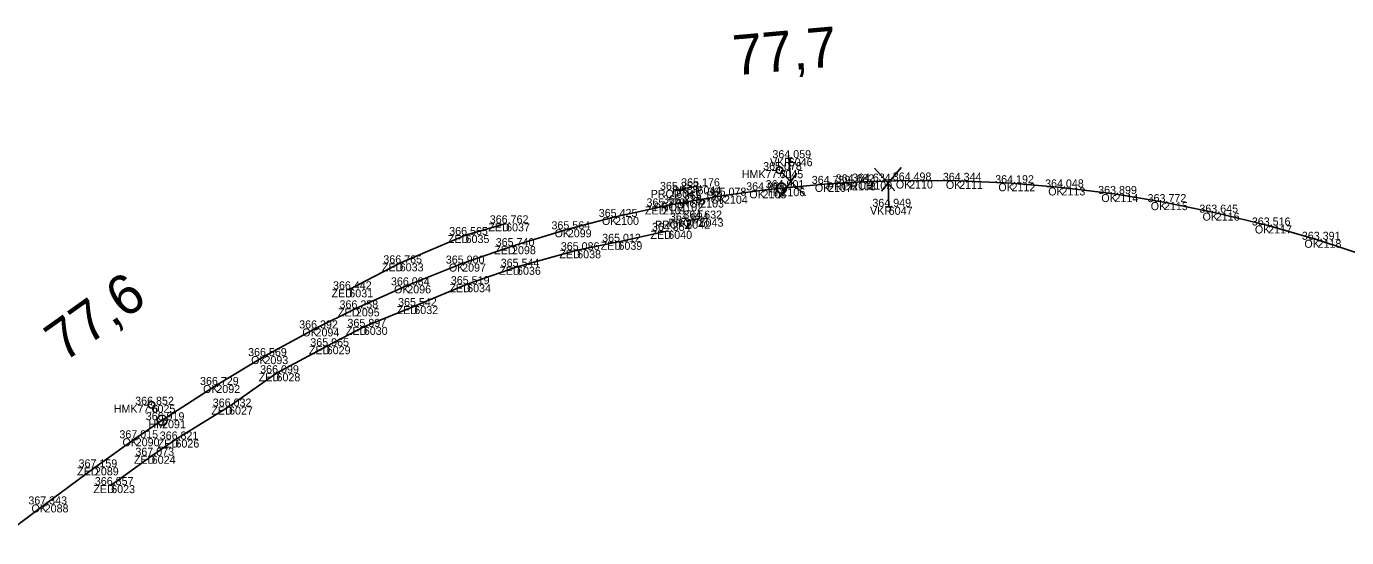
# Model space of a CAD drawing. Extents: x -621782 to -610392, y -1141853 to -1122321.
# Drawn here: x -616534.2 to -616336.3, y -1130256.3 to -1130179.7 of the extents above; entities that cross this region are included whole.
import ezdxf

# ---------------------------------------------------------------- set-up
doc = ezdxf.new("R2010")
doc.units = 0
for name, color, linetype in [('Vrstva 1', 7, 'Continuous'), ('Vrstva 13', 7, 'Continuous'), ('Vrstva 19', 7, 'Continuous'), ('Vrstva 4', 7, 'Continuous'), ('Vrstva 60', 7, 'Continuous'), ('Vrstva 61', 7, 'Continuous'), ('Vrstva 62', 7, 'Continuous'), ('Vrstva 7', 7, 'Continuous')]:
    doc.layers.add(name, color=color, linetype=linetype)

msp = doc.modelspace()

# ---------------------------------------------------------------- linework, layer by layer
at = {"layer": 'Vrstva 1'}
msp.add_lwpolyline([(-616538.07, -1130256.29), (-616531.48, -1130251.32), (-616523.95, -1130245.77), (-616517.83, -1130241.41), (-616513.88, -1130238.71), (-616505.74, -1130233.43), (-616498.53, -1130229.1), (-616490.87, -1130224.95), (-616484.82, -1130221.95), (-616477.11, -1130218.5), (-616468.88, -1130215.24), (-616461.4, -1130212.63), (-616453.04, -1130210.1), (-616445.94, -1130208.25), (-616438.79, -1130206.67), (-616436.33, -1130206.2), (-616433.19, -1130205.64), (-616429.62, -1130205.06), (-616423.84, -1130204.26), (-616421.01, -1130203.94), (-616414.01, -1130203.3), (-616410.42, -1130203.07), (-616407.97, -1130202.95), (-616401.86, -1130202.79), (-616394.36, -1130202.84), (-616386.5, -1130203.2), (-616379.01, -1130203.83), (-616371.06, -1130204.81), (-616363.65, -1130206.03), (-616355.88, -1130207.61), (-616348.02, -1130209.53), (-616340.61, -1130211.67), (-616333.02, -1130214.2)], dxfattribs=at)
at = {"layer": 'Vrstva 13'}
for points in [[(-616437.97, -1130210.33), (-616445.44, -1130211.97), (-616451.63, -1130213.24), (-616460.65, -1130215.72), (-616468.13, -1130218.33), (-616476.05, -1130221.6), (-616483.63, -1130224.72), (-616489.19, -1130227.62), (-616496.72, -1130231.67), (-616503.83, -1130236.66), (-616511.87, -1130241.6), (-616515.43, -1130244.03), (-616521.51, -1130248.43)], [(-616485.8, -1130219.1), (-616478.24, -1130215.2), (-616468.37, -1130210.96), (-616462.29, -1130209.21)]]:
    msp.add_lwpolyline(points, dxfattribs=at)
at = {"layer": 'Vrstva 19'}
for p, q in [((-616436.77, -1130204.2), (-616433.59, -1130203.66)), ((-616435.27, -1130208.81), (-616433.27, -1130208.5))]:
    msp.add_line(p, q, dxfattribs=at)
at = {"layer": 'Vrstva 4'}
for p, q in [((-616419.41, -1130199.4), (-616420.41, -1130199.49)), ((-616419.91, -1130199.45), (-616419.6, -1130202.95)), ((-616407.07, -1130200.93), (-616403.98, -1130204.35)), ((-616405.98, -1130204.4), (-616403.07, -1130200.82)), ((-616418.7, -1130201.7), (-616421.38, -1130205.45)), ((-616417.39, -1130205.1), (-616420.7, -1130201.88)), ((-616410.42, -1130203.07), (-616407.97, -1130202.95)), ((-616404.92, -1130206.73), (-616405.01, -1130203.21)), ((-616405.42, -1130206.74), (-616404.42, -1130206.71))]:
    msp.add_line(p, q, dxfattribs=at)
at = {"layer": 'Vrstva 60'}
for p, q in [((-616419.91, -1130199.45), (-616419.91, -1130199.45)), ((-616421.3, -1130201.24), (-616421.3, -1130201.24)), ((-616407.97, -1130202.95), (-616407.97, -1130202.95)), ((-616401.86, -1130202.79), (-616401.86, -1130202.79)), ((-616394.36, -1130202.84), (-616394.36, -1130202.84)), ((-616436.77, -1130204.2), (-616436.77, -1130204.2)), ((-616433.59, -1130203.66), (-616433.59, -1130203.66)), ((-616423.84, -1130204.26), (-616423.84, -1130204.26)), ((-616421.01, -1130203.94), (-616421.01, -1130203.94)), ((-616414.01, -1130203.3), (-616414.01, -1130203.3)), ((-616410.42, -1130203.07), (-616410.42, -1130203.07)), ((-616386.5, -1130203.2), (-616386.5, -1130203.2)), ((-616379.01, -1130203.83), (-616379.01, -1130203.83)), ((-616371.06, -1130204.81), (-616371.06, -1130204.81)), ((-616438.79, -1130206.67), (-616438.79, -1130206.67)), ((-616436.33, -1130206.2), (-616436.33, -1130206.2)), ((-616433.19, -1130205.64), (-616433.19, -1130205.64)), ((-616429.62, -1130205.06), (-616429.62, -1130205.06)), ((-616404.92, -1130206.73), (-616404.92, -1130206.73)), ((-616363.65, -1130206.03), (-616363.65, -1130206.03)), ((-616445.94, -1130208.25), (-616445.94, -1130208.25)), ((-616435.27, -1130208.81), (-616435.27, -1130208.81)), ((-616433.27, -1130208.5), (-616433.27, -1130208.5)), ((-616355.88, -1130207.61), (-616355.88, -1130207.61)), ((-616462.29, -1130209.21), (-616462.29, -1130209.21)), ((-616453.04, -1130210.1), (-616453.04, -1130210.1)), ((-616437.97, -1130210.33), (-616437.97, -1130210.33)), ((-616348.02, -1130209.53), (-616348.02, -1130209.53)), ((-616468.37, -1130210.96), (-616468.37, -1130210.96)), ((-616461.4, -1130212.63), (-616461.4, -1130212.63)), ((-616445.44, -1130211.97), (-616445.44, -1130211.97)), ((-616340.61, -1130211.67), (-616340.61, -1130211.67)), ((-616451.63, -1130213.24), (-616451.63, -1130213.24)), ((-616478.24, -1130215.2), (-616478.24, -1130215.2)), ((-616468.88, -1130215.24), (-616468.88, -1130215.24)), ((-616460.65, -1130215.72), (-616460.65, -1130215.72)), ((-616477.11, -1130218.5), (-616477.11, -1130218.5)), ((-616468.13, -1130218.33), (-616468.13, -1130218.33)), ((-616485.8, -1130219.1), (-616485.8, -1130219.1)), ((-616484.82, -1130221.95), (-616484.82, -1130221.95)), ((-616476.05, -1130221.6), (-616476.05, -1130221.6)), ((-616483.63, -1130224.72), (-616483.63, -1130224.72)), ((-616490.87, -1130224.95), (-616490.87, -1130224.95)), ((-616489.19, -1130227.62), (-616489.19, -1130227.62)), ((-616498.53, -1130229.1), (-616498.53, -1130229.1)), ((-616496.72, -1130231.67), (-616496.72, -1130231.67)), ((-616505.74, -1130233.43), (-616505.74, -1130233.43)), ((-616515.46, -1130236.39), (-616515.46, -1130236.39)), ((-616503.83, -1130236.66), (-616503.83, -1130236.66)), ((-616513.88, -1130238.71), (-616513.88, -1130238.71)), ((-616517.83, -1130241.41), (-616517.83, -1130241.41)), ((-616511.87, -1130241.6), (-616511.87, -1130241.6)), ((-616515.43, -1130244.03), (-616515.43, -1130244.03)), ((-616523.95, -1130245.77), (-616523.95, -1130245.77)), ((-616521.51, -1130248.43), (-616521.51, -1130248.43)), ((-616531.48, -1130251.32), (-616531.48, -1130251.32))]:
    msp.add_line(p, q, dxfattribs=at)
at = {"layer": 'Vrstva 7'}
for p, q in [((-616421.35, -1130201.25), (-616421.25, -1130201.24)), ((-616515.5, -1130236.42), (-616515.42, -1130236.36))]:
    msp.add_line(p, q, dxfattribs=at)
for centre, radius in [((-616421.3, -1130201.24), 0.5), ((-616421.01, -1130203.94), 0.75), ((-616515.46, -1130236.39), 0.5), ((-616513.88, -1130238.71), 0.75)]:
    msp.add_circle(centre, radius, dxfattribs=at)

# ---------------------------------------------------------------- texts
at = {"layer": 'Vrstva 60'}
for s, p in [('6046', (-616419.91, -1130200.65)), ('6045', (-616421.3, -1130202.44)), ('2109', (-616407.97, -1130204.15)), ('2110', (-616401.86, -1130203.99)), ('2111', (-616394.36, -1130204.04)), ('6041', (-616436.77, -1130205.4)), ('6044', (-616433.59, -1130204.86)), ('2105', (-616423.84, -1130205.46)), ('2106', (-616421.01, -1130205.14)), ('2107', (-616414.01, -1130204.5)), ('2108', (-616410.42, -1130204.27)), ('2112', (-616386.5, -1130204.4)), ('2113', (-616379.01, -1130205.03)), ('2114', (-616371.06, -1130206.02)), ('2101', (-616438.79, -1130207.87)), ('2102', (-616436.33, -1130207.4)), ('2103', (-616433.19, -1130206.84)), ('2104', (-616429.62, -1130206.26)), ('6047', (-616404.92, -1130207.93)), ('2115', (-616363.65, -1130207.23)), ('2100', (-616445.94, -1130209.45)), ('6042', (-616435.27, -1130210.01)), ('6043', (-616433.27, -1130209.7)), ('2116', (-616355.88, -1130208.81)), ('6037', (-616462.29, -1130210.41)), ('2099', (-616453.04, -1130211.3)), ('6040', (-616437.97, -1130211.53)), ('2117', (-616348.02, -1130210.73)), ('6035', (-616468.37, -1130212.16)), ('2098', (-616461.4, -1130213.83)), ('6039', (-616445.44, -1130213.17)), ('2118', (-616340.61, -1130212.87)), ('6038', (-616451.63, -1130214.44)), ('6033', (-616478.24, -1130216.4)), ('2097', (-616468.88, -1130216.44)), ('6036', (-616460.65, -1130216.92)), ('2096', (-616477.11, -1130219.7)), ('6034', (-616468.13, -1130219.53)), ('6031', (-616485.8, -1130220.3)), ('2095', (-616484.82, -1130223.15)), ('6032', (-616476.05, -1130222.8)), ('6030', (-616483.63, -1130225.92)), ('2094', (-616490.87, -1130226.15)), ('6029', (-616489.19, -1130228.82)), ('2093', (-616498.53, -1130230.3)), ('6028', (-616496.72, -1130232.87)), ('2092', (-616505.74, -1130234.63)), ('6025', (-616515.46, -1130237.59)), ('6027', (-616503.83, -1130237.86)), ('2091', (-616513.88, -1130239.91)), ('2090', (-616517.83, -1130242.61)), ('6026', (-616511.87, -1130242.8)), ('6024', (-616515.43, -1130245.23)), ('2089', (-616523.95, -1130246.97)), ('6023', (-616521.51, -1130249.63)), ('2088', (-616531.48, -1130252.52))]:
    msp.add_text(s, height=1.2, dxfattribs=at).set_placement(p)
at = {"layer": 'Vrstva 61'}
for s, p in [('364.059', (-616422.36, -1130199.45)), ('365.078', (-616423.75, -1130201.24)), ('365.176', (-616436.04, -1130203.66)), ('364.901', (-616423.37, -1130203.94)), ('364.759', (-616416.46, -1130203.3)), ('364.682', (-616412.87, -1130203.07)), ('364.634', (-616410.42, -1130202.95)), ('364.498', (-616404.32, -1130202.79)), ('364.344', (-616396.81, -1130202.84)), ('364.192', (-616388.95, -1130203.2)), ('364.048', (-616381.47, -1130203.83)), ('365.253', (-616439.22, -1130204.2)), ('365.150', (-616435.64, -1130205.64)), ('365.078', (-616432.07, -1130205.06)), ('364.958', (-616426.29, -1130204.26)), ('363.899', (-616373.51, -1130204.81)), ('363.772', (-616366.1, -1130206.03)), ('365.270', (-616441.24, -1130206.67)), ('365.216', (-616438.78, -1130206.2)), ('364.949', (-616407.37, -1130206.73)), ('363.645', (-616358.34, -1130207.61)), ('366.762', (-616464.74, -1130209.21)), ('365.564', (-616455.49, -1130210.1)), ('365.425', (-616448.4, -1130208.25)), ('364.694', (-616437.72, -1130208.81)), ('364.632', (-616435.71, -1130208.5)), ('363.516', (-616350.47, -1130209.53)), ('366.565', (-616470.82, -1130210.96)), ('365.012', (-616447.89, -1130211.97)), ('364.854', (-616440.42, -1130210.33)), ('363.391', (-616342.97, -1130211.67)), ('365.740', (-616463.85, -1130212.63)), ('365.086', (-616454.09, -1130213.24)), ('366.765', (-616480.7, -1130215.2)), ('365.900', (-616471.33, -1130215.24)), ('365.544', (-616463.1, -1130215.72)), ('366.442', (-616488.25, -1130219.1)), ('366.084', (-616479.56, -1130218.5)), ('365.519', (-616470.58, -1130218.33)), ('366.258', (-616487.27, -1130221.95)), ('365.542', (-616478.49, -1130221.6)), ('366.392', (-616493.32, -1130224.95)), ('365.897', (-616486.08, -1130224.72)), ('365.965', (-616491.65, -1130227.62)), ('366.569', (-616500.98, -1130229.1)), ('366.099', (-616499.17, -1130231.67)), ('366.729', (-616508.19, -1130233.43)), ('366.852', (-616517.91, -1130236.39)), ('366.032', (-616506.28, -1130236.66)), ('366.919', (-616516.33, -1130238.71)), ('367.015', (-616520.28, -1130241.41)), ('366.821', (-616514.23, -1130241.6)), ('367.073', (-616517.88, -1130244.03)), ('367.159', (-616526.4, -1130245.77)), ('366.857', (-616523.96, -1130248.43)), ('367.343', (-616533.93, -1130251.32))]:
    msp.add_text(s, height=1.2, dxfattribs=at).set_placement(p)
at = {"layer": 'Vrstva 62'}
for s, p in [('VKR', (-616422.72, -1130200.65)), ('HMK77.7', (-616426.96, -1130202.44)), ('PRCH', (-616411.75, -1130204.15)), ('OK', (-616403.85, -1130203.99)), ('OK', (-616396.35, -1130204.04)), ('PROP', (-616440.61, -1130205.4)), ('PROP', (-616437.42, -1130204.86)), ('OK', (-616425.82, -1130205.46)), ('HM', (-616423.04, -1130205.14)), ('OK', (-616415.99, -1130204.5)), ('PRCH', (-616414.2, -1130204.27)), ('OK', (-616388.48, -1130204.4)), ('OK', (-616381, -1130205.03)), ('OK', (-616373.04, -1130206.02)), ('ZED', (-616441.46, -1130207.87)), ('PROP', (-616440.16, -1130207.4)), ('PROP', (-616437.03, -1130206.84)), ('OK', (-616431.6, -1130206.26)), ('VKR', (-616407.72, -1130207.93)), ('OK', (-616365.63, -1130207.23)), ('OK', (-616447.92, -1130209.45)), ('PROPZ', (-616439.97, -1130210.01)), ('PROPZ', (-616437.97, -1130209.7)), ('OK', (-616357.86, -1130208.81)), ('ZED', (-616464.96, -1130210.41)), ('OK', (-616455.02, -1130211.3)), ('ZED', (-616440.65, -1130211.53)), ('OK', (-616350.01, -1130210.73)), ('ZED', (-616471.04, -1130212.16)), ('ZED', (-616464.07, -1130213.83)), ('ZED', (-616448.11, -1130213.17)), ('OK', (-616342.59, -1130212.87)), ('ZED', (-616454.31, -1130214.44)), ('ZED', (-616480.91, -1130216.4)), ('OK', (-616470.87, -1130216.44)), ('ZED', (-616463.32, -1130216.92)), ('OK', (-616479.09, -1130219.7)), ('ZED', (-616470.8, -1130219.53)), ('ZED', (-616488.48, -1130220.3)), ('ZED', (-616487.49, -1130223.15)), ('ZED', (-616478.72, -1130222.8)), ('ZED', (-616486.31, -1130225.92)), ('OK', (-616492.85, -1130226.15)), ('ZED', (-616491.86, -1130228.82)), ('OK', (-616500.52, -1130230.3)), ('ZED', (-616499.39, -1130232.87)), ('OK', (-616507.73, -1130234.63)), ('HMK77.6', (-616521.13, -1130237.59)), ('ZED', (-616506.5, -1130237.86)), ('HM', (-616515.91, -1130239.91)), ('OK', (-616519.81, -1130242.61)), ('ZED', (-616514.54, -1130242.8)), ('ZED', (-616518.1, -1130245.23)), ('ZED', (-616526.62, -1130246.97)), ('ZED', (-616524.18, -1130249.63)), ('OK', (-616533.46, -1130252.52))]:
    msp.add_text(s, height=1.2, dxfattribs=at).set_placement(p)
at = {"layer": 'Vrstva 7'}
for s, rotation, p in [('77,7', 5.1465, (-616428.02, -1130187.05)), ('77,6', 35.4508, (-616528.61, -1130230.12))]:
    msp.add_text(s, height=6, rotation=rotation, dxfattribs=at).set_placement(p)

doc.saveas('drawing.dxf')
